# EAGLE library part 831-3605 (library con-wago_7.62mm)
Serie 831, Stiftleiste (für Leiterplatten) mit geraden Einlötstiften / Series 831, Male header (for PCBs) with straight solder pins Polzahl / Pole No.: 5 Bemessungsspannung / Rated Voltage: 630 V Nennstrom / Nominal Current: 41 A Lötstiftlänge: / Solder Pin Length: 4 mm Farbe / Color: lichtgrau / light gray Stand: 01.01.2012. Die jeweils aktuellen Daten zu diesem Artikel finden Sie in unserem Produktkatalog, den Sie unter www.wago.com einsehen können. As of: 01/01/2012. Please find the newest data for this article in our product catalogue, which can be viewed under www.wago.com.
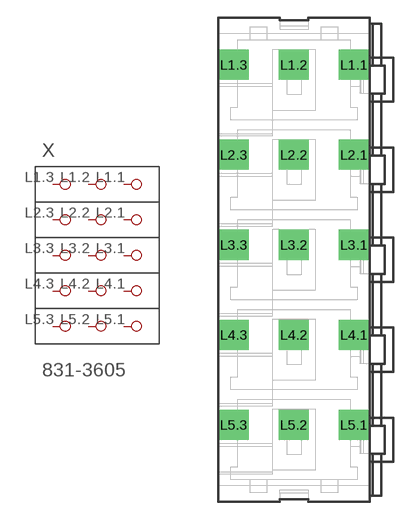
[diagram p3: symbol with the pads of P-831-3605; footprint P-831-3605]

Designator prefix X

## 831-3605  [P-831-3605]
L1.1  P1.1
L1.2  P1.2
L1.3  P1.3
L2.1  P2.1
L2.2  P2.2
L2.3  P2.3
L3.1  P3.1
L3.2  P3.2
L3.3  P3.3
L4.1  P4.1
L4.2  P4.2
L4.3  P4.3
L5.1  P5.1
L5.2  P5.2
L5.3  P5.3

## Footprint P-831-3605 (pad centres in mm)
drill 1.7 square: L1.1 4.08,16.51; L1.2 -1,16.51; L1.3 -6.08,16.51; L2.1 4.08,8.89; L2.2 -1,8.89; L2.3 -6.08,8.89; L3.1 4.08,1.27; L3.2 -1,1.27; L3.3 -6.08,1.27; L4.1 4.08,-6.35; L4.2 -1,-6.35; L4.3 -6.08,-6.35; L5.1 4.07,-13.97; L5.2 -1.01,-13.97; L5.3 -6.09,-13.97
